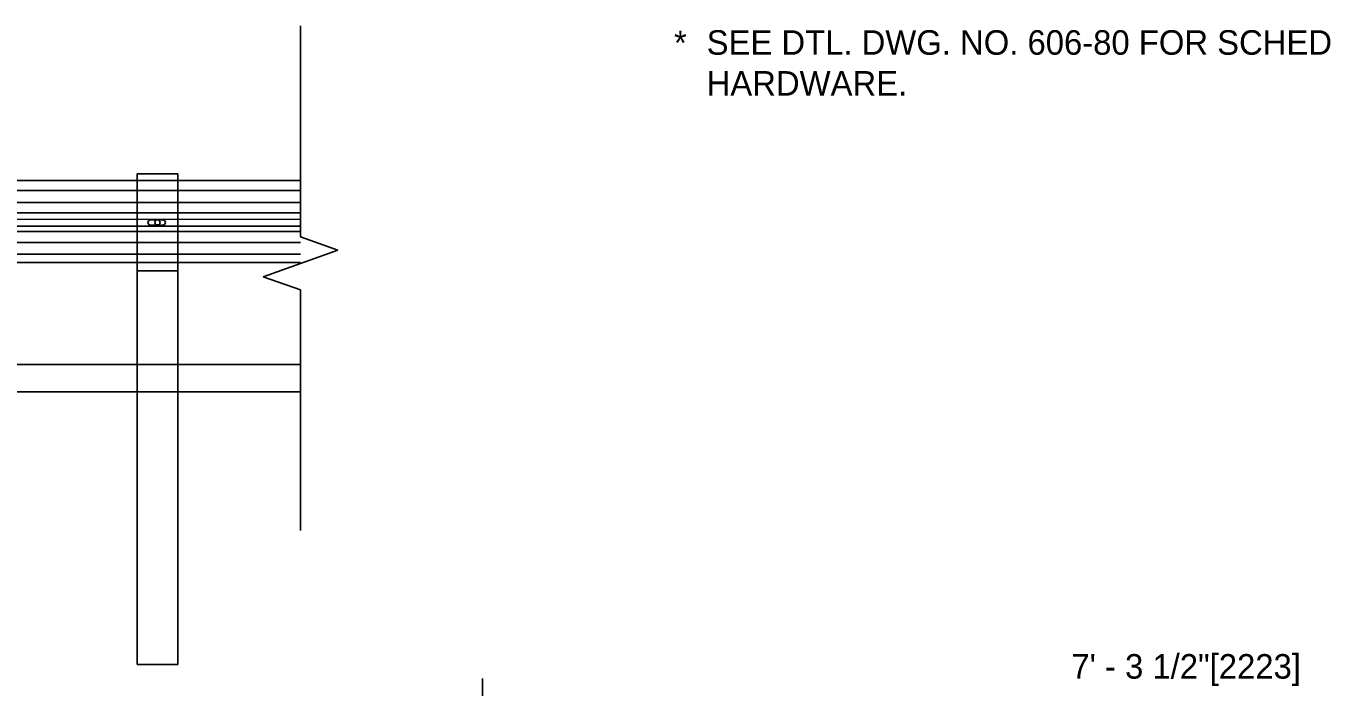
# Model space of a CAD drawing. Extents: x 49991 to 50160, y 49948 to 50051.
# Drawn here: x 50011 to 50014.17, y 49994.263 to 49995.88 of the extents above; entities that cross this region are included whole.
import ezdxf

# ---------------------------------------------------------------- set-up
doc = ezdxf.new("R2010")
doc.units = 0
for name, color, linetype in [('Level 1', 7, 'Continuous'), ('Level 2', 7, 'Continuous'), ('Level 3', 7, 'Continuous'), ('Level 4', 7, 'Continuous'), ('Level 6', 7, 'Continuous')]:
    doc.layers.add(name, color=color, linetype=linetype)

msp = doc.modelspace()

# ---------------------------------------------------------------- linework, layer by layer
at = {"layer": 'Level 1'}
for p, q in [((50011.2716, 49995.5181), (50011.2716, 49995.5019)), ((50011.2716, 49995.5181), (50011.3716, 49995.5181)), ((50011.2716, 49995.5181), (50011.2716, 49995.5014)), ((50011.2716, 49995.5181), (50011.3716, 49995.5181)), ((50011.3716, 49995.5181), (50011.3716, 49995.5014)), ((50011.3716, 49995.5181), (50011.3716, 49995.5015)), ((50004.3866, 49995.5019), (50011.6716, 49995.5014)), ((50004.5497, 49995.4776), (50011.6716, 49995.4776)), ((50004.5497, 49995.4485), (50011.6716, 49995.4479)), ((50004.5497, 49995.4214), (50011.6716, 49995.4224)), ((50005.0854, 49995.4089), (50011.6716, 49995.4067)), ((50011.6716, 49995.3901), (50005.5897, 49995.3902)), ((50011.6716, 49995.3772), (50005.5897, 49995.3772)), ((50011.305, 49995.4056), (50011.3345, 49995.4056)), ((50011.3345, 49995.3925), (50011.305, 49995.3925)), ((50011.6716, 49995.3503), (50005.5897, 49995.3503)), ((50011.6716, 49995.3213), (50005.5897, 49995.3213)), ((50011.6716, 49995.3011), (50005.5897, 49995.3011)), ((50011.2716, 49995.0514), (50011.2716, 49995.3011)), ((50011.2716, 49995.3008), (50011.2716, 49995.2806)), ((50011.3716, 49995.0514), (50011.3716, 49995.3011)), ((50011.3716, 49995.3008), (50011.3716, 49995.2806)), ((50011.2716, 49995.2806), (50011.3716, 49995.2806)), ((50011.6716, 49995.0514), (50000.8008, 49995.0519)), ((49999.8072, 49994.9853), (50011.6716, 49994.9848))]:
    msp.add_line(p, q, dxfattribs=at)
msp.add_circle((50011.3216, 49995.3994), 0.00625, dxfattribs=at)
for centre, start, end in [((50011.305, 49995.3991), 90, 270), ((50011.3345, 49995.3991), 270, 90)]:
    msp.add_arc(centre, 0.00656, start, end, dxfattribs=at)
at = {"layer": 'Level 3'}
msp.add_line((50012.1168, 49993.5214), (50012.1168, 49994.2833), dxfattribs=at)
at = {"layer": 'Level 4'}
for p, q in [((50011.2716, 49995.3011), (50011.2716, 49995.5019)), ((50011.2716, 49995.3008), (50011.2716, 49995.5014)), ((50011.3716, 49995.3011), (50011.3716, 49995.5019)), ((50011.3716, 49995.3008), (50011.3716, 49995.5015)), ((50011.2716, 49995.0514), (50011.2716, 49994.9848)), ((50011.3716, 49995.0514), (50011.3716, 49994.9848)), ((50011.2716, 49994.9848), (50011.2716, 49994.3181)), ((50011.3716, 49994.9848), (50011.3716, 49994.3181)), ((50011.2716, 49994.3181), (50011.3716, 49994.3181))]:
    msp.add_line(p, q, dxfattribs=at)
at = {"layer": 'Level 6'}
for p, q in [((50011.6716, 49995.3637), (50011.6716, 49995.8799)), ((50011.6716, 49995.3637), (50011.763, 49995.3313)), ((50011.6716, 49995.2989), (50011.763, 49995.3313)), ((50011.5802, 49995.2665), (50011.6716, 49995.2989)), ((50011.5802, 49995.2665), (50011.6716, 49995.2341)), ((50011.6716, 49995.2341), (50011.6716, 49994.6458))]:
    msp.add_line(p, q, dxfattribs=at)

# ---------------------------------------------------------------- texts
at = {"layer": 'Level 2'}
for s, p in [('*', (50012.5848, 49995.8084)), ('SEE DTL. DWG. NO. 606-80 FOR SCHEDULE OF GUARDRAIL ', (50012.6646, 49995.8094)), ('HARDWARE.', (50012.6646, 49995.7094)), ('7\' - 3 1/2"[2223]', (50013.5565, 49994.2833))]:
    msp.add_text(s, height=0.06, dxfattribs=at).set_placement(p)

doc.saveas('drawing.dxf')
